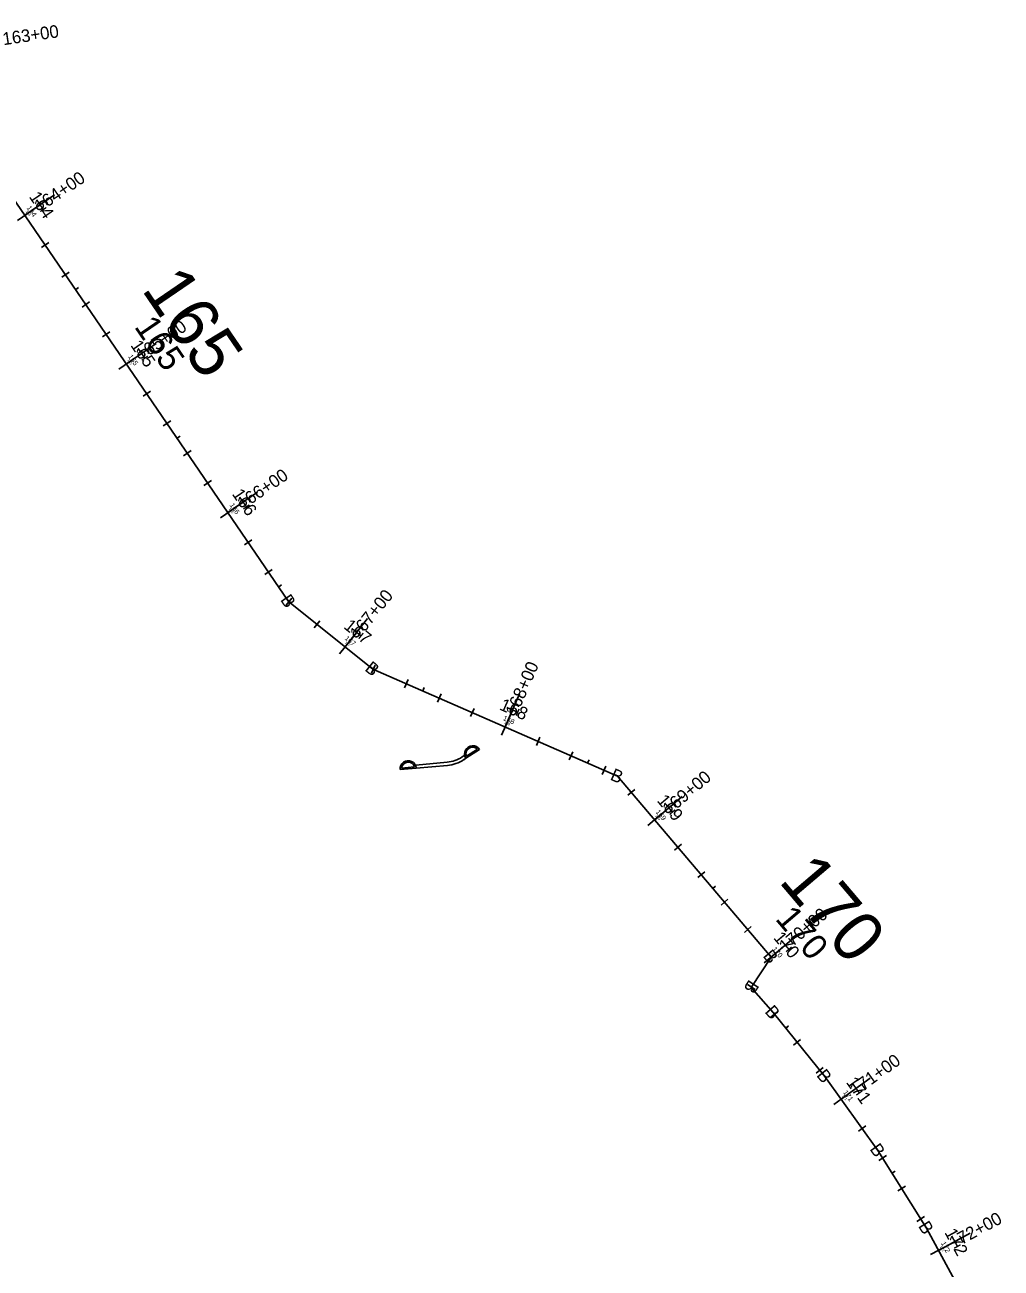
# Model space of a CAD drawing. Extents: x 1823824 to 1861612, y 706975 to 726130.
# Drawn here: x 1826149 to 1826692, y 714585 to 715276 of the extents above; entities that cross this region are included whole.
import ezdxf

# ---------------------------------------------------------------- set-up
doc = ezdxf.new("R2010")
doc.units = 0
for name, color, linetype in [('DR_X_Flood_Boundary', 7, 'Continuous'), ('GE_X_CL_10', 7, 'Continuous'), ('GE_X_CL_100', 7, 'Continuous'), ('GE_X_CL_20', 7, 'Continuous'), ('GE_X_CL_200', 7, 'Continuous'), ('GE_X_CL_50', 7, 'Continuous'), ('SC_Scratch5', 7, 'Continuous'), ('SC_Scratch6', 7, 'Continuous')]:
    doc.layers.add(name, color=color, linetype=linetype)

msp = doc.modelspace()

# ---------------------------------------------------------------- linework, layer by layer
at = {"layer": 'DR_X_Flood_Boundary'}
for p, q in [((1826141.7, 715180.65), (1826295.66, 714955.3)), ((1826295.66, 714955.3), (1826342.5, 714917.79)), ((1826342.5, 714917.79), (1826478.5, 714858.3)), ((1826394.21, 714868.24), (1826401.74, 714873.17)), ((1826394.49, 714869.32), (1826400.64, 714873.35)), ((1826358.38, 714862.77), (1826365.7, 714863.42)), ((1826383.74, 714866.05), (1826366.43, 714864.49)), ((1826366.43, 714864.49), (1826366.59, 714862.75)), ((1826383.9, 714864.3), (1826366.59, 714862.75)), ((1826392.1, 714868.95), (1826393.25, 714869.71)), ((1826392.97, 714867.43), (1826394.21, 714868.24)), ((1826393.25, 714869.71), (1826394.21, 714868.24)), ((1826357.62, 714861.95), (1826366.59, 714862.75)), ((1826478.5, 714858.3), (1826563.81, 714757.86)), ((1826563.81, 714757.86), (1826552.64, 714740.86)), ((1826552.64, 714740.86), (1826564.87, 714726.95)), ((1826564.87, 714726.95), (1826593.6, 714691.51)), ((1826593.6, 714691.51), (1826623.17, 714650.33)), ((1826623.17, 714650.33), (1826650.11, 714607.32)), ((1826650.11, 714607.32), (1826671.86, 714567.14))]:
    msp.add_line(p, q, dxfattribs=at)
for centre, radius, start, end in [((1826397.97, 714870.71), 4.5, 33.18851, 213.20223), ((1826397.97, 714870.71), 3.75, 44.71918, 201.67444), ((1826362.11, 714862.35), 4.5, 5.12773, 185.14144), ((1826362.11, 714862.35), 3.75, 16.65839, 173.61366), ((1826382.11, 714884.22), 18.25, 275.12647, 303.20232), ((1826382.11, 714884.22), 20, 275.12739, 303.19438)]:
    msp.add_arc(centre, radius, start, end, dxfattribs=at)
at = {"layer": 'GE_X_CL_10'}
for p, q in [((1826149.12, 715169.79), (1826149.95, 715170.36)), ((1826177.33, 715128.51), (1826178.15, 715129.07)), ((1826205.53, 715087.22), (1826206.36, 715087.79)), ((1826233.74, 715045.94), (1826234.56, 715046.5)), ((1826261.94, 715004.65), (1826262.77, 715005.22)), ((1826290.15, 714963.37), (1826290.98, 714963.93)), ((1826327.06, 714930.15), (1826327.69, 714930.94)), ((1826370.19, 714905.68), (1826370.59, 714906.6)), ((1826416, 714885.64), (1826416.4, 714886.56)), ((1826461.81, 714865.6), (1826462.21, 714866.52)), ((1826499.08, 714834.08), (1826499.84, 714834.73)), ((1826531.44, 714795.97), (1826532.21, 714796.62)), ((1826563.81, 714757.86), (1826564.58, 714758.51)), ((1826571.88, 714718.3), (1826572.66, 714718.93)), ((1826602.65, 714678.91), (1826603.46, 714679.5)), ((1826631.03, 714637.78), (1826631.88, 714638.31)), ((1826656.8, 714594.95), (1826657.68, 714595.43))]:
    msp.add_line(p, q, dxfattribs=at)
at = {"layer": 'GE_X_CL_100'}
for p, q in [((1826149.12, 715169.79), (1826157.38, 715175.43)), ((1826205.53, 715087.22), (1826213.79, 715092.86)), ((1826261.94, 715004.65), (1826270.2, 715010.29)), ((1826327.06, 714930.15), (1826333.31, 714937.96)), ((1826416, 714885.64), (1826420.01, 714894.8)), ((1826499.08, 714834.08), (1826506.7, 714840.55)), ((1826563.81, 714757.86), (1826571.44, 714764.34)), ((1826602.65, 714678.91), (1826610.77, 714684.75)), ((1826656.8, 714594.95), (1826665.6, 714599.71))]:
    msp.add_line(p, q, dxfattribs=at)
at = {"layer": 'GE_X_CL_20'}
for p, q in [((1826149.12, 715169.79), (1826150.77, 715170.92)), ((1826177.33, 715128.51), (1826178.98, 715129.64)), ((1826205.53, 715087.22), (1826207.18, 715088.35)), ((1826233.74, 715045.94), (1826235.39, 715047.07)), ((1826261.94, 715004.65), (1826263.6, 715005.78)), ((1826290.15, 714963.37), (1826291.8, 714964.5)), ((1826327.06, 714930.15), (1826328.31, 714931.72)), ((1826370.19, 714905.68), (1826370.99, 714907.51)), ((1826416, 714885.64), (1826416.8, 714887.47)), ((1826461.81, 714865.6), (1826462.61, 714867.44)), ((1826499.08, 714834.08), (1826500.6, 714835.37)), ((1826531.44, 714795.97), (1826532.97, 714797.27)), ((1826563.81, 714757.86), (1826565.34, 714759.16)), ((1826571.88, 714718.3), (1826573.43, 714719.56)), ((1826602.65, 714678.91), (1826604.27, 714680.08)), ((1826631.03, 714637.78), (1826632.73, 714638.84)), ((1826656.8, 714594.95), (1826658.56, 714595.91))]:
    msp.add_line(p, q, dxfattribs=at)
at = {"layer": 'GE_X_CL_200'}
for p, q in [((1826149.12, 715169.79), (1826165.64, 715181.07)), ((1826205.53, 715087.22), (1826222.05, 715098.51)), ((1826261.94, 715004.65), (1826278.46, 715015.94)), ((1826327.06, 714930.15), (1826339.56, 714945.77)), ((1826416, 714885.64), (1826424.02, 714903.97)), ((1826499.08, 714834.08), (1826514.32, 714847.03)), ((1826563.81, 714757.86), (1826579.06, 714770.81)), ((1826602.65, 714678.91), (1826618.89, 714690.58)), ((1826656.8, 714594.95), (1826674.39, 714604.48))]:
    msp.add_line(p, q, dxfattribs=at)
at = {"layer": 'GE_X_CL_50'}
for p, q in [((1826149.12, 715169.79), (1826153.25, 715172.61)), ((1826205.53, 715087.22), (1826209.66, 715090.04)), ((1826261.94, 715004.65), (1826266.07, 715007.47)), ((1826327.06, 714930.15), (1826330.19, 714934.06)), ((1826416, 714885.64), (1826418, 714890.22)), ((1826499.08, 714834.08), (1826502.89, 714837.32)), ((1826563.81, 714757.86), (1826567.63, 714761.1)), ((1826602.65, 714678.91), (1826606.71, 714681.83)), ((1826656.8, 714594.95), (1826661.2, 714597.33))]:
    msp.add_line(p, q, dxfattribs=at)
at = {"layer": 'SC_Scratch5'}
for points in [[(1826153.25, 715172.61), (1826144.99, 715166.97)], [(1826162.47, 715154.69), (1826158.34, 715151.87)], [(1826173.75, 715138.17), (1826169.62, 715135.35)], [(1826185.03, 715121.66), (1826180.9, 715118.84)], [(1826196.32, 715105.15), (1826192.19, 715102.33)], [(1826209.66, 715090.04), (1826201.4, 715084.4)], [(1826218.88, 715072.12), (1826214.75, 715069.3)], [(1826230.16, 715055.61), (1826226.03, 715052.78)], [(1826241.44, 715039.09), (1826237.32, 715036.27)], [(1826252.73, 715022.58), (1826248.6, 715019.76)], [(1826266.07, 715007.47), (1826257.82, 715001.83)], [(1826275.29, 714989.55), (1826271.16, 714986.73)], [(1826286.57, 714973.04), (1826282.44, 714970.22)], [(1826297.4, 714957.11), (1826294.28, 714953.21)], [(1826313.01, 714944.61), (1826309.89, 714940.7)], [(1826330.19, 714934.06), (1826323.94, 714926.25)], [(1826343.71, 714919.99), (1826341.7, 714915.41)], [(1826362.03, 714911.98), (1826360.03, 714907.4)], [(1826380.35, 714903.96), (1826378.35, 714899.38)], [(1826398.68, 714895.95), (1826396.67, 714891.37)], [(1826418, 714890.22), (1826414, 714881.06)], [(1826435.33, 714879.92), (1826433.32, 714875.34)], [(1826453.65, 714871.9), (1826451.65, 714867.32)], [(1826471.97, 714863.89), (1826469.97, 714859.31)], [(1826488.03, 714850.94), (1826484.22, 714847.7)], [(1826502.89, 714837.32), (1826495.26, 714830.84)], [(1826513.93, 714820.45), (1826510.12, 714817.22)], [(1826526.88, 714805.21), (1826523.07, 714801.97)], [(1826539.82, 714789.97), (1826536.01, 714786.73)], [(1826552.77, 714774.73), (1826548.96, 714771.49)], [(1826567.63, 714761.1), (1826560, 714754.63)], [(1826554.92, 714739.78), (1826550.74, 714742.52)], [(1826567.52, 714727.64), (1826563.64, 714724.5)], [(1826580.12, 714712.11), (1826576.23, 714708.96)], [(1826592.71, 714696.57), (1826588.83, 714693.42)], [(1826606.71, 714681.83), (1826598.58, 714676)], [(1826616.34, 714664.13), (1826612.28, 714661.21)], [(1826627.84, 714647.58), (1826623.61, 714644.93)], [(1826638.46, 714630.63), (1826634.22, 714627.98)], [(1826649.08, 714613.68), (1826644.84, 714611.03)], [(1826661.2, 714597.33), (1826652.41, 714592.57)]]:
    msp.add_lwpolyline(points, dxfattribs=at)

# ---------------------------------------------------------------- texts
at = {"layer": 'GE_X_CL_10'}
for s, rotation, p in [('164', 304.3408, (1826149.53, 715171.85)), ('165', 304.3408, (1826205.94, 715089.29)), ('166', 304.3408, (1826262.34, 715006.73)), ('167', 321.31409, (1826326.82, 714932.27)), ('168', 336.37331, (1826415.27, 714887.6)), ('169', 310.34504, (1826499.26, 714836.18)), ('170', 310.34504, (1826564, 714759.96)), ('171', 305.68409, (1826603.15, 714680.78)), ('172', 298.43204, (1826657.43, 714596.94))]:
    msp.add_text(s, height=1.4, rotation=rotation, dxfattribs=at).set_placement(p)
at = {"layer": 'GE_X_CL_100'}
for s, rotation, p in [('165', 304.3408, (1826209.56, 715107.92)), ('170', 310.34504, (1826565.65, 714778.87))]:
    msp.add_text(s, height=14, rotation=rotation, dxfattribs=at).set_placement(p)
at = {"layer": 'GE_X_CL_20'}
for s, rotation, p in [('164', 304.3408, (1826149.95, 715173.91)), ('165', 304.3408, (1826206.34, 715091.36)), ('166', 304.3408, (1826262.74, 715008.8)), ('167', 321.31409, (1826326.57, 714934.39)), ('168', 336.37331, (1826414.54, 714889.56)), ('169', 310.34504, (1826499.45, 714838.27)), ('170', 310.34504, (1826564.18, 714762.07)), ('171', 305.68409, (1826603.66, 714682.64)), ('172', 298.43204, (1826658.06, 714598.93))]:
    msp.add_text(s, height=2.8, rotation=rotation, dxfattribs=at).set_placement(p)
at = {"layer": 'GE_X_CL_200'}
for s, rotation, p in [('165', 304.3408, (1826213.58, 715128.62)), ('170', 310.34504, (1826567.49, 714799.88))]:
    msp.add_text(s, height=28, rotation=rotation, dxfattribs=at).set_placement(p)
at = {"layer": 'GE_X_CL_50'}
for s, rotation, p in [('164', 304.3408, (1826151.18, 715180.07)), ('165', 304.3408, (1826207.55, 715097.57)), ('166', 304.3408, (1826263.94, 715015.03)), ('167', 321.31409, (1826325.84, 714940.74)), ('168', 336.37331, (1826412.34, 714895.43)), ('169', 310.34504, (1826500.01, 714844.56)), ('170', 310.34504, (1826564.73, 714768.37)), ('171', 305.68409, (1826605.19, 714688.23)), ('172', 298.43204, (1826659.95, 714604.9))]:
    msp.add_text(s, height=7, rotation=rotation, dxfattribs=at).set_placement(p)
at = {"layer": 'SC_Scratch5'}
for s, rotation, p in [('163+00', 8.23126, (1826137.19, 715264.22)), ('164+00', 34.3408, (1826157.29, 715171.13)), ('165+00', 34.3408, (1826213.7, 715088.56)), ('166+00', 34.3408, (1826270.11, 715005.99)), ('167+00', 51.31409, (1826334.48, 714933.82)), ('168+00', 66.37331, (1826422.21, 714891.11)), ('169+00', 40.34504, (1826507.06, 714836.27)), ('170+00', 40.34504, (1826571.8, 714760.05)), ('171+00', 35.68409, (1826610.78, 714680.44)), ('172+00', 28.43204, (1826665.07, 714595.45))]:
    msp.add_text(s, height=7, rotation=rotation, dxfattribs=at).set_placement(p)
at = {"layer": 'SC_Scratch6'}
for rotation, p in [(304.3408, (1826290.8, 714956.21)), (321.31409, (1826337.58, 714917.25)), (336.37331, (1826473.89, 714856.5)), (310.34504, (1826558.88, 714758.27)), (236.69135, (1826551.64, 714745.71)), (311.32186, (1826559.93, 714727.27)), (309.03082, (1826588.68, 714692.02)), (305.68409, (1826618.29, 714651.13)), (302.05762, (1826645.29, 714608.43))]:
    msp.add_text('B', height=7, rotation=rotation, dxfattribs=at).set_placement(p)

doc.saveas('drawing.dxf')
